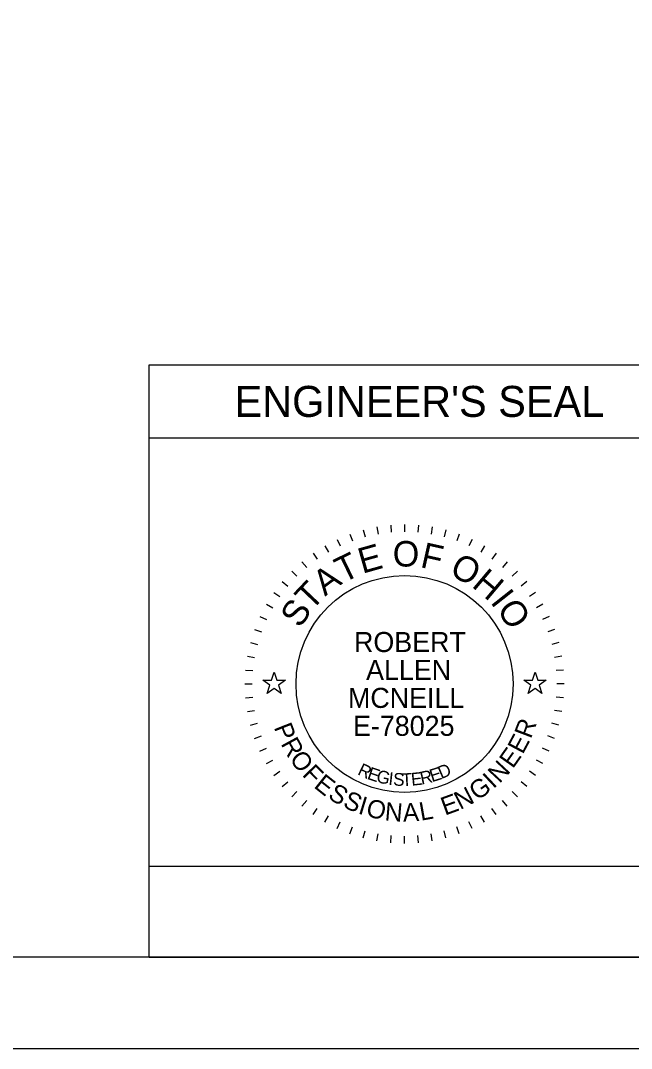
# Model space of a CAD drawing. Extents: x -7.1 to 34, y 0 to 22.
# Drawn here: x 6.64 to 9.99, y 0 to 5.64 of the extents above; entities that cross this region are included whole.
import ezdxf

# ---------------------------------------------------------------- set-up
doc = ezdxf.new("R2010")
doc.units = 0
for name, color, linetype in [('Default', 7, 'Continuous'), ('SH_Border', 7, 'Continuous'), ('SH_Cut_Line', 7, 'Continuous'), ('SH_Data', 7, 'Continuous')]:
    doc.layers.add(name, color=color, linetype=linetype)

msp = doc.modelspace()

# ---------------------------------------------------------------- linework, layer by layer
at = {"layer": 'Default'}
for points in [[(7.9736, 2.02), (8.0205, 2.02), (8.035, 2.0645), (8.0495, 2.02), (8.0964, 2.02), (8.0585, 1.9924), (8.073, 1.9478), (8.035, 1.9754), (7.997, 1.9478), (8.0115, 1.9924)], [(9.4036, 2.02), (9.4505, 2.02), (9.465, 2.0645), (9.4795, 2.02), (9.5264, 2.02), (9.4885, 1.9924), (9.503, 1.9478), (9.465, 1.9754), (9.427, 1.9478), (9.4415, 1.9924)]]:
    msp.add_lwpolyline(points, close=True, dxfattribs=at)
at = {"layer": 'SH_Border'}
msp.add_lwpolyline([(1.5, 21.5), (33.5, 21.5), (33.5, 0.5), (1.5, 0.5)], close=True, dxfattribs=at)
at = {"layer": 'SH_Cut_Line'}
msp.add_lwpolyline([(0, 0), (34, 0), (34, 22), (0, 22)], close=True, dxfattribs=at)
at = {"layer": 'SH_Data'}
for p, q in [((7.35, 0.5), (7.35, 3.75)), ((7.35, 3.75), (10.15, 3.75)), ((7.35, 3.35), (10.15, 3.35)), ((8.4507, 2.8222), (8.4644, 2.7846)), ((8.5235, 2.8452), (8.5339, 2.8065)), ((8.5981, 2.8617), (8.605, 2.8223)), ((8.6737, 2.8717), (8.6772, 2.8318)), ((8.75, 2.875), (8.75, 2.835)), ((8.8263, 2.8717), (8.8228, 2.8318)), ((8.9019, 2.8617), (8.895, 2.8223)), ((8.9765, 2.8452), (8.9661, 2.8065)), ((9.0493, 2.8222), (9.0356, 2.7846)), ((8.3802, 2.793), (8.3971, 2.7568)), ((9.1198, 2.793), (9.1029, 2.7568)), ((8.2481, 2.7168), (8.2711, 2.684)), ((8.3125, 2.7578), (8.3325, 2.7231)), ((9.1875, 2.7578), (9.1675, 2.7231)), ((9.2519, 2.7168), (9.2289, 2.684)), ((8.1876, 2.6703), (8.2133, 2.6396)), ((9.3124, 2.6703), (9.2867, 2.6396)), ((8.1313, 2.6187), (8.1596, 2.5904)), ((9.3687, 2.6187), (9.3404, 2.5904)), ((8.0797, 2.5624), (8.1104, 2.5367)), ((9.4203, 2.5624), (9.3896, 2.5367)), ((8.0332, 2.5019), (8.066, 2.4789)), ((9.4668, 2.5019), (9.434, 2.4789)), ((7.9922, 2.4375), (8.0269, 2.4175)), ((9.5078, 2.4375), (9.4731, 2.4175)), ((7.957, 2.3698), (7.9932, 2.3529)), ((9.543, 2.3698), (9.5068, 2.3529)), ((7.9278, 2.2993), (7.9654, 2.2856)), ((9.5722, 2.2993), (9.5346, 2.2856)), ((7.9048, 2.2265), (7.9435, 2.2161)), ((9.5952, 2.2265), (9.5565, 2.2161)), ((7.8883, 2.1519), (7.9277, 2.145)), ((9.6117, 2.1519), (9.5723, 2.145)), ((7.8783, 2.0763), (7.9182, 2.0728)), ((9.6217, 2.0763), (9.5818, 2.0728)), ((7.875, 2), (7.915, 2)), ((9.625, 2), (9.585, 2)), ((7.8783, 1.9237), (7.9182, 1.9272)), ((9.6217, 1.9237), (9.5818, 1.9272)), ((7.8883, 1.8481), (7.9277, 1.855)), ((9.6117, 1.8481), (9.5723, 1.855)), ((7.9048, 1.7735), (7.9435, 1.7839)), ((9.5952, 1.7735), (9.5565, 1.7839)), ((7.9278, 1.7007), (7.9654, 1.7144)), ((9.5722, 1.7007), (9.5346, 1.7144)), ((7.957, 1.6302), (7.9932, 1.6471)), ((9.543, 1.6302), (9.5068, 1.6471)), ((7.9922, 1.5625), (8.0269, 1.5825)), ((9.5078, 1.5625), (9.4731, 1.5825)), ((8.0332, 1.4981), (8.066, 1.5211)), ((9.4668, 1.4981), (9.434, 1.5211)), ((8.0797, 1.4376), (8.1104, 1.4633)), ((9.4203, 1.4376), (9.3896, 1.4633)), ((8.1313, 1.3813), (8.1596, 1.4096)), ((8.1876, 1.3297), (8.2133, 1.3604)), ((9.3124, 1.3297), (9.2867, 1.3604)), ((9.3687, 1.3813), (9.3404, 1.4096)), ((8.2481, 1.2832), (8.2711, 1.316)), ((9.2519, 1.2832), (9.2289, 1.316)), ((8.3125, 1.2422), (8.3325, 1.2769)), ((8.3802, 1.207), (8.3971, 1.2432)), ((9.1198, 1.207), (9.1029, 1.2432)), ((9.1875, 1.2422), (9.1675, 1.2769)), ((8.4507, 1.1778), (8.4644, 1.2154)), ((8.5235, 1.1548), (8.5339, 1.1935)), ((8.9765, 1.1548), (8.9661, 1.1935)), ((9.0493, 1.1778), (9.0356, 1.2154)), ((8.5981, 1.1383), (8.605, 1.1777)), ((8.6737, 1.1283), (8.6772, 1.1682)), ((8.75, 1.125), (8.75, 1.165)), ((8.8263, 1.1283), (8.8228, 1.1682)), ((8.9019, 1.1383), (8.895, 1.1777)), ((7.35, 0.5), (10.15, 0.5))]:
    msp.add_line(p, q, dxfattribs=at)
msp.add_lwpolyline([(7.35, 0.5), (7.35, 1), (10.15, 1), (10.15, 0.5)], close=True, dxfattribs=at)
msp.add_circle((8.75, 2), 0.595, dxfattribs=at)

# ---------------------------------------------------------------- texts
for s, height, p in [("ENGINEER'S SEAL", 0.17, (7.8176, 3.465)), ('ROBERT', 0.11, (8.4728, 2.1749)), ('ALLEN', 0.11, (8.5389, 2.0216)), ('MCNEILL', 0.11, (8.4398, 1.8684)), ('E-78025', 0.11, (8.4673, 1.7151))]:
    msp.add_text(s, height=height, dxfattribs=at).set_placement(p)
for s, height, rotation, p in [('E', 0.14, 15.7571, (8.5184, 2.6038)), ('O', 0.14, 359.7812, (8.6847, 2.6443)), ('F', 0.14, 347.4362, (8.8311, 2.6417)), ('T', 0.14, 25.7167, (8.4116, 2.5518)), ('O', 0.14, 332.2586, (8.9898, 2.6015)), ('A', 0.14, 36.4747, (8.3134, 2.4781)), ('H', 0.14, 319.9136, (9.1132, 2.5361)), ('T', 0.14, 46.4344, (8.2383, 2.3964)), ('I', 0.14, 308.367, (9.2165, 2.4483)), ('S', 0.14, 57.1924, (8.1781, 2.3014)), ('O', 0.14, 303.1491, (9.2521, 2.4089)), ('R', 0.1, 69.2322, (9.4419, 1.6954)), ('P', 0.1, 291.494, (8.0323, 1.7621)), ('R', 0.1, 298.7311, (8.069, 1.6717)), ('E', 0.1, 61.9951, (9.3976, 1.6098)), ('E', 0.1, 54.758, (9.3433, 1.5314)), ('O', 0.1, 306.4666, (8.1155, 1.5883)), ('N', 0.1, 47.0224, (9.2702, 1.4508)), ('F', 0.1, 314.7068, (8.1843, 1.4983)), ('R', 0.07, 334.487, (8.4875, 1.5051)), ('E', 0.07, 341.04, (8.5406, 1.4801)), ('G', 0.07, 347.4752, (8.5914, 1.4618)), ('R', 0.07, 11.9184, (8.8425, 1.4474)), ('E', 0.07, 17.6836, (8.8998, 1.4602)), ('D', 0.07, 23.3052, (8.951, 1.477)), ('E', 0.1, 321.4393, (8.2478, 1.4348)), ('I', 0.07, 353.7858, (8.6591, 1.4468)), ('S', 0.07, 356.8926, (8.6858, 1.4429)), ('T', 0.07, 3.0061, (8.7357, 1.4387)), ('E', 0.07, 6.0117, (8.7889, 1.4412)), ('G', 0.1, 35.0469, (9.1481, 1.357)), ('I', 0.1, 43.287, (9.2368, 1.4214)), ('S', 0.1, 328.6764, (8.3243, 1.3752)), ('N', 0.1, 27.3113, (9.0545, 1.3075)), ('S', 0.1, 335.9134, (8.4064, 1.3266)), ('I', 0.1, 343.1505, (8.4906, 1.2897)), ('O', 0.1, 346.8859, (8.5339, 1.2751)), ('E', 0.1, 20.0742, (8.9712, 1.277)), ('N', 0.1, 355.1261, (8.6388, 1.2517)), ('A', 0.1, 2.8617, (8.7423, 1.2437)), ('L', 0.1, 10.0987, (8.8394, 1.249))]:
    msp.add_text(s, height=height, rotation=rotation, dxfattribs=at).set_placement(p)

doc.saveas('drawing.dxf')
